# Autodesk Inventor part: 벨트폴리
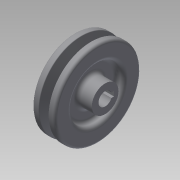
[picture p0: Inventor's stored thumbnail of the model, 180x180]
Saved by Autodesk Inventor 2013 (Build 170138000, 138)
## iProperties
Created: 2015-02
Part Number: 벨트폴리
Material: 일반
Document SubType Name: Modeling
Designer: Administrator
Density: 1 g/cm^3
Author: Administrator
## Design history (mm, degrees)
sketch "스케치1"
  geometry: L1 (0, 0)-(25, 0); L2 (0, 5.5)-(0, 11); L3 (0, 11)-(6, 11); L4 (0, 35.2)-(5.5, 35.2); L5 (13.5, 35.2)-(19, 35.2); L6 (13, 11)-(25, 11); L7 (25, 11)-(25, 5.5); L8 (25, 5.5)-(0, 5.5); L9 (5.5, 35.2)-(8.252, 26.2); L10 (8.252, 26.2)-(10.748, 26.2); L11 (10.748, 26.2)-(13.5, 35.2); L12 (19, 35.2)-(19, 21.5); L13 (19, 21.5)-(13, 21.5); L14 (0, 35.2)-(0, 21.5); L15 (0, 21.5)-(6, 21.5); L16 (13, 21.5)-(13, 11); L17 (6, 21.5)-(6, 11); 8 further points
  constraints: 34 end point, 8 midpoint, 7 perpendicular, 5 parallel, 3 horizontal alignment, 2 equal length, 2 vertical alignment, 1 collinear, 1 horizontal
  dimensions: "d5" = 25 distance of L1.start L1.end; "d6" = 11 diameter of L8 L1; "d7" = 22 diameter of L6 L1; "d8" = 19 distance of L5.end L4.start; "d9" = 25 distance from line of L7 L4.start; "d10" = 70.4 diameter of L4 L1; "d11" = 8 distance of L5.start L4.end; "d12" = 34 deg angle of L11 L9; "d14" = 9 distance between parallel lines of L10 L5; "d17" = 43 diameter of L15 L1; "d19" = 6 distance between parallel lines of L2 L17; "d20" = 7 distance between parallel lines of L16 L17
revolve "회전1" sketch "스케치1" stored, may be unused: angle "d21" = 90 deg
sketch "스케치2"
  geometry: L1 (-2, 7.3)-(2, 7.3); L2 (-2, 7.3)-(-2, 5.123); L3 (2, 7.3)-(2, 5.123); C1 r 11 at (0, 0) reference; A1 r 5.5 centre (0, 0) between (-2, 5.123) and (2, 5.123) reference; A2 r 5.5 centre (0, 0) between (2, 5.123) and (-2, 5.123); 1 further point
  constraints: 6 end point, 4 point on circle, 1 centre point, 1 coincident, 1 concentric, 1 horizontal, 1 midpoint, 1 parallel, 1 perpendicular, 1 vertical alignment
  dimensions: "d22" = 4 distance of L1.start L1.end; "d23" = 12.8 dimension on A1 L1
extrude "돌출1" cut sketch "스케치2" stored distance "d24" = 10; taper "d25" = 0 deg
fillet "모깎기1" dims "d26" = 2, "d27" = 0.5, "d28" = 1, "d29" = 3
node "솔리드1"
